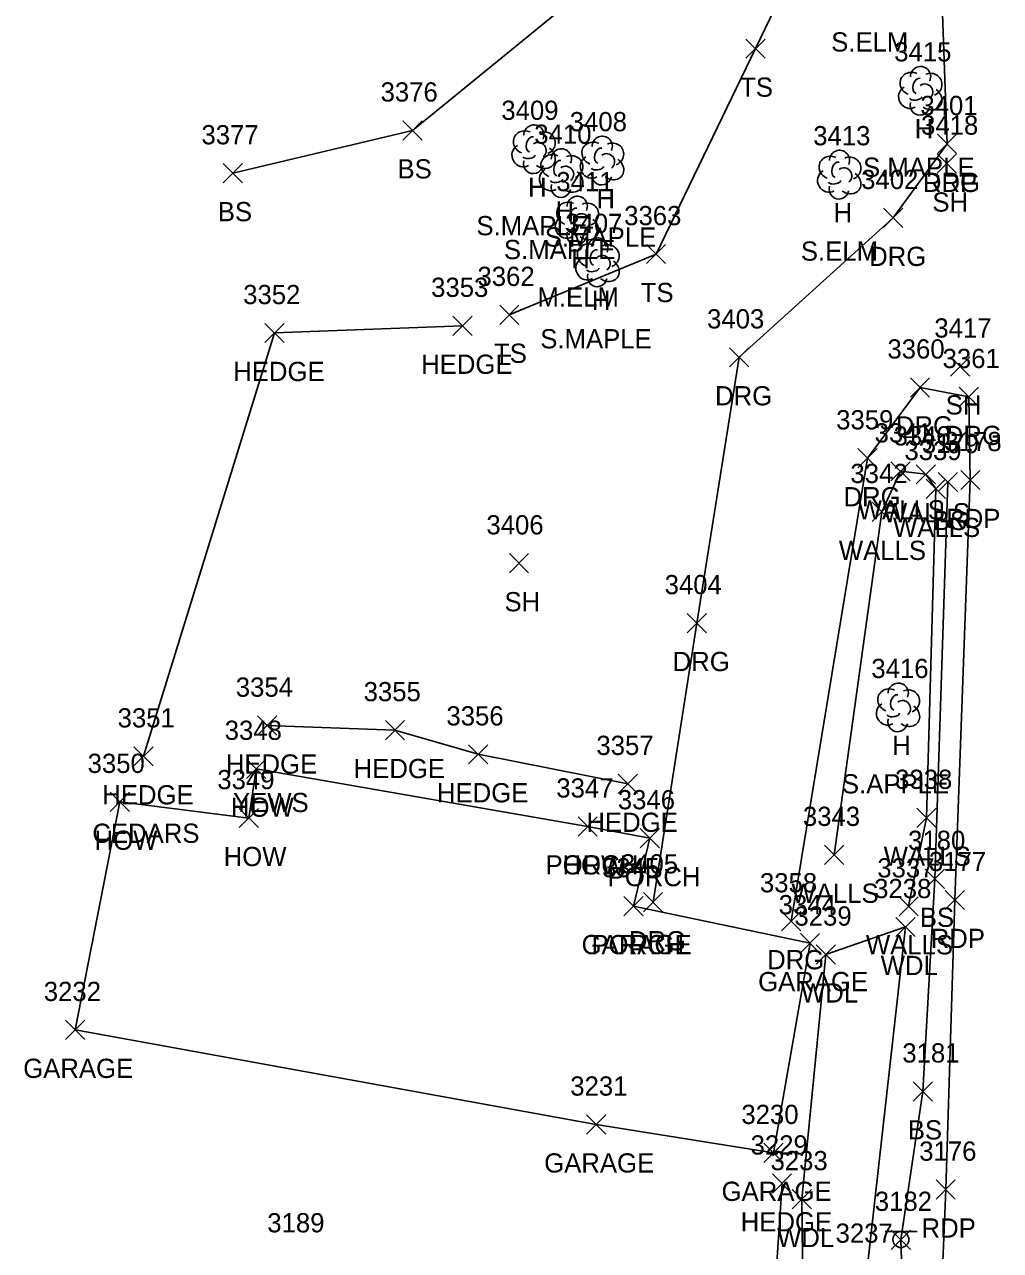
# Model space of a CAD drawing. Extents: x 1609623 to 1616187, y 756677 to 762826.
# Drawn here: x 1610505.2 to 1610606.7, y 762355.6 to 762483.1 of the extents above; entities that cross this region are included whole.
import ezdxf

# ---------------------------------------------------------------- set-up
doc = ezdxf.new("R2010")
doc.units = 0
for name, color, linetype in [('L_A', 7, 'Continuous'), ('L_C', 7, 'Continuous'), ('L_I', 7, 'Continuous'), ('L_TIC', 7, 'Continuous'), ('LAHR', 7, 'Continuous'), ('LAWA', 7, 'Continuous'), ('LBC', 7, 'Continuous'), ('LBF', 7, 'Continuous'), ('LELB', 7, 'Continuous'), ('LTD', 7, 'Continuous'), ('LWS', 7, 'Continuous'), ('P_A', 7, 'Continuous'), ('P_I', 7, 'Continuous'), ('P_TIC', 7, 'Continuous'), ('PET', 7, 'Continuous'), ('R_A', 7, 'Continuous'), ('R_I', 7, 'Continuous'), ('R_TIC', 7, 'Continuous'), ('RDG', 7, 'Continuous'), ('S_I', 7, 'Continuous'), ('SSGN', 7, 'Continuous')]:
    doc.layers.add(name, color=color, linetype=linetype)

msp = doc.modelspace()

# ---------------------------------------------------------------- linework, layer by layer
at = {"layer": 'L_TIC'}
for points in [[(1610580.23, 762479.58), (1610582.23, 762481.58)], [(1610582.23, 762479.58), (1610580.23, 762481.58)], [(1610544.56, 762471.08), (1610546.56, 762473.08)], [(1610546.56, 762471.08), (1610544.56, 762473.08)], [(1610600.15, 762467.63), (1610602.15, 762469.63)], [(1610602.15, 762467.63), (1610600.15, 762469.63)], [(1610525.87, 762466.63), (1610527.87, 762468.63)], [(1610527.87, 762466.63), (1610525.87, 762468.63)], [(1610569.89, 762458.22), (1610571.89, 762460.22)], [(1610571.89, 762458.22), (1610569.89, 762460.22)], [(1610554.63, 762451.9), (1610556.63, 762453.9)], [(1610556.63, 762451.9), (1610554.63, 762453.9)], [(1610530.21, 762450.01), (1610532.21, 762452.01)], [(1610532.21, 762450.01), (1610530.21, 762452.01)], [(1610549.76, 762450.76), (1610551.76, 762452.76)], [(1610551.76, 762450.76), (1610549.76, 762452.76)], [(1610601.53, 762446.53), (1610603.53, 762448.53)], [(1610603.53, 762446.53), (1610601.53, 762448.53)], [(1610595.32, 762435.62), (1610597.32, 762437.62)], [(1610597.32, 762435.62), (1610595.32, 762437.62)], [(1610597.95, 762435.31), (1610599.95, 762437.31)], [(1610599.95, 762435.31), (1610597.95, 762437.31)], [(1610600.24, 762434.51), (1610602.24, 762436.51)], [(1610602.24, 762434.51), (1610600.24, 762436.51)], [(1610599, 762433.79), (1610601, 762435.79)], [(1610601, 762433.79), (1610599, 762435.79)], [(1610593.37, 762431.4), (1610595.37, 762433.4)], [(1610595.37, 762431.4), (1610593.37, 762433.4)], [(1610555.64, 762426.06), (1610557.64, 762428.06)], [(1610557.64, 762426.06), (1610555.64, 762428.06)], [(1610529.44, 762409.18), (1610531.44, 762411.18)], [(1610531.44, 762409.18), (1610529.44, 762411.18)], [(1610542.74, 762408.71), (1610544.74, 762410.71)], [(1610544.74, 762408.71), (1610542.74, 762410.71)], [(1610516.59, 762405.98), (1610518.59, 762407.98)], [(1610518.59, 762405.98), (1610516.59, 762407.98)], [(1610551.4, 762406.19), (1610553.4, 762408.19)], [(1610553.4, 762406.19), (1610551.4, 762408.19)], [(1610528.29, 762404.69), (1610530.29, 762406.69)], [(1610530.29, 762404.69), (1610528.29, 762406.69)], [(1610566.95, 762403.12), (1610568.95, 762405.12)], [(1610568.95, 762403.12), (1610566.95, 762405.12)], [(1610514.11, 762401.25), (1610516.11, 762403.25)], [(1610516.11, 762401.25), (1610514.11, 762403.25)], [(1610527.53, 762399.56), (1610529.53, 762401.56)], [(1610529.53, 762399.56), (1610527.53, 762401.56)], [(1610598.02, 762399.59), (1610600.02, 762401.59)], [(1610600.02, 762399.59), (1610598.02, 762401.59)], [(1610562.78, 762398.69), (1610564.78, 762400.69)], [(1610564.78, 762398.69), (1610562.78, 762400.69)], [(1610562.78, 762398.69), (1610564.78, 762400.69)], [(1610564.78, 762398.69), (1610562.78, 762400.69)], [(1610569.24, 762397.47), (1610571.24, 762399.47)], [(1610571.24, 762397.47), (1610569.24, 762399.47)], [(1610588.43, 762395.74), (1610590.43, 762397.74)], [(1610590.43, 762395.74), (1610588.43, 762397.74)], [(1610598.89, 762393.24), (1610600.89, 762395.24)], [(1610600.89, 762393.24), (1610598.89, 762395.24)], [(1610567.55, 762390.4), (1610569.55, 762392.4)], [(1610569.55, 762390.4), (1610567.55, 762392.4)], [(1610567.55, 762390.4), (1610569.55, 762392.4)], [(1610569.55, 762390.4), (1610567.55, 762392.4)], [(1610596.17, 762390.38), (1610598.17, 762392.38)], [(1610598.17, 762390.38), (1610596.17, 762392.38)], [(1610595.84, 762388.23), (1610597.84, 762390.23)], [(1610597.84, 762388.23), (1610595.84, 762390.23)], [(1610585.91, 762386.55), (1610587.91, 762388.55)], [(1610587.91, 762386.55), (1610585.91, 762388.55)], [(1610587.56, 762385.37), (1610589.56, 762387.37)], [(1610589.56, 762385.37), (1610587.56, 762387.37)], [(1610509.47, 762377.53), (1610511.47, 762379.53)], [(1610511.47, 762377.53), (1610509.47, 762379.53)], [(1610597.64, 762371.13), (1610599.64, 762373.13)], [(1610599.64, 762371.13), (1610597.64, 762373.13)], [(1610563.67, 762367.69), (1610565.67, 762369.69)], [(1610565.67, 762367.69), (1610563.67, 762369.69)], [(1610582.11, 762364.74), (1610584.11, 762366.74)], [(1610584.11, 762364.74), (1610582.11, 762366.74)], [(1610583, 762361.56), (1610585, 762363.56)], [(1610585, 762361.56), (1610583, 762363.56)], [(1610585.06, 762359.93), (1610587.06, 762361.93)], [(1610587.06, 762359.93), (1610585.06, 762361.93)], [(1610595.35, 762355.7), (1610597.35, 762357.7)], [(1610597.35, 762355.7), (1610595.35, 762357.7)]]:
    msp.add_lwpolyline(points, dxfattribs=at)
at = {"layer": 'LAHR'}
for points in [[(1610517.59, 762406.98), (1610531.21, 762451.01), (1610550.76, 762451.76)], [(1610530.44, 762410.18), (1610543.74, 762409.71), (1610552.4, 762407.19), (1610567.95, 762404.12)], [(1610582.46, 762307.18), (1610581.3, 762322.56), (1610584, 762362.56)]]:
    msp.add_lwpolyline(points, dxfattribs=at)
at = {"layer": 'LAWA'}
for points in [[(1610586.06, 762360.93), (1610586.43, 762328.14), (1610588.36, 762309.19), (1610592.62, 762314.71), (1610592.83, 762353.39), (1610596.84, 762389.23), (1610588.56, 762386.37)], [(1610588.56, 762386.37), (1610586.06, 762360.93)]]:
    msp.add_lwpolyline(points, dxfattribs=at)
at = {"layer": 'LBC'}
for points in [[(1610563.78, 762399.69), (1610529.29, 762405.69), (1610528.53, 762400.56), (1610515.11, 762402.25)], [(1610515.11, 762402.25), (1610510.47, 762378.53)], [(1610586.91, 762387.55), (1610568.55, 762391.4)], [(1610586.91, 762387.55), (1610583.11, 762365.74)], [(1610583.11, 762365.74), (1610564.67, 762368.69), (1610510.47, 762378.53)]]:
    msp.add_lwpolyline(points, dxfattribs=at)
at = {"layer": 'LBF'}
msp.add_lwpolyline([(1610568.55, 762391.4), (1610570.24, 762398.47), (1610563.78, 762399.69)], dxfattribs=at)
at = {"layer": 'LELB'}
for points in [[(1610555.63, 762452.9), (1610570.89, 762459.22), (1610581.23, 762480.58), (1610591.33, 762501.51), (1610590.52, 762530.81), (1610583.83, 762554.19), (1610570.39, 762605.11)], [(1610574.84, 762534.79), (1610575.41, 762508.59), (1610574.59, 762505.74), (1610568.05, 762490.43), (1610545.56, 762472.08), (1610526.87, 762467.63)], [(1610601.24, 762435.51), (1610599.89, 762394.24), (1610598.64, 762372.13), (1610596.35, 762356.7), (1610597.27, 762330.15), (1610594.16, 762309.47), (1610581.81, 762305.45), (1610558.47, 762312.1), (1610535.64, 762323.35), (1610518.75, 762343.55), (1610533.17, 762354.47)]]:
    msp.add_lwpolyline(points, dxfattribs=at)
at = {"layer": 'LTD'}
for p, q in [((1610598.36, 762476.25), (1610598.36, 762476.25)), ((1610598.36, 762476.25), (1610598.36, 762476.25)), ((1610558.14, 762470.17), (1610558.14, 762470.17)), ((1610558.14, 762470.17), (1610558.14, 762470.17)), ((1610565.26, 762468.99), (1610565.26, 762468.99)), ((1610565.26, 762468.99), (1610565.26, 762468.99)), ((1610561, 762467.69), (1610561, 762467.69)), ((1610561, 762467.69), (1610561, 762467.69)), ((1610589.93, 762467.53), (1610589.93, 762467.53)), ((1610589.93, 762467.53), (1610589.93, 762467.53)), ((1610562.65, 762462.75), (1610562.65, 762462.75)), ((1610562.65, 762462.75), (1610562.65, 762462.75)), ((1610564.79, 762458.41), (1610564.79, 762458.41)), ((1610564.79, 762458.41), (1610564.79, 762458.41)), ((1610596.04, 762412.12), (1610596.04, 762412.12)), ((1610596.04, 762412.12), (1610596.04, 762412.12))]:
    msp.add_line(p, q, dxfattribs=at)
for centre in [(1610598.41, 762477.68), (1610558.19, 762471.6), (1610565.3, 762470.43), (1610561.05, 762469.12), (1610589.98, 762468.96), (1610562.7, 762464.18), (1610564.84, 762459.84), (1610596.09, 762413.55)]:
    msp.add_arc(centre, 1.05, 335.5272, 180.9563, dxfattribs=at)
for centre, major_axis, ratio, start_param, end_param in [((1610597.57, 762476.92), (1.21, -0.51), 0.895232, 1.570796, 4.712389), ((1610598.16, 762476.71), (-0.208, -0.792), 0.645439, 3.141593, 6.283185), ((1610599.41, 762476.83), (-1.14, -0.48), 0.949671, 1.570796, 4.712389), ((1610597.28, 762475.54), (0.58, -1.04), 0.959034, 3.141593, 6.283185), ((1610598.86, 762476.08), (-0.5, 0.667), 0.989748, 3.141593, 6.283185), ((1610599.36, 762475.42), (-1.09, 0.79), 0.841452, 1.570796, 4.712389), ((1610598.36, 762474.75), (0.26, 1.06), 0.942809, 1.570796, 4.712389), ((1610597.91, 762475.5), (-0.625, -0.083), 0.423636, 0, 3.141593), ((1610557.35, 762470.83), (1.21, -0.51), 0.895232, 1.570796, 4.712389), ((1610557.94, 762470.62), (-0.208, -0.792), 0.645439, 3.141593, 6.283185), ((1610558.64, 762470), (-0.5, 0.667), 0.989748, 3.141593, 6.283185), ((1610559.19, 762470.75), (-1.14, -0.48), 0.949671, 1.570796, 4.712389), ((1610564.47, 762469.66), (1.21, -0.51), 0.895232, 1.570796, 4.712389), ((1610566.3, 762469.58), (-1.14, -0.48), 0.949671, 1.570796, 4.712389), ((1610557.06, 762469.46), (0.58, -1.04), 0.959034, 3.141593, 6.283185), ((1610559.14, 762469.33), (-1.09, 0.79), 0.841452, 1.570796, 4.712389), ((1610560.21, 762468.36), (1.21, -0.51), 0.895232, 1.570796, 4.712389), ((1610562.05, 762468.27), (-1.14, -0.48), 0.949671, 1.570796, 4.712389), ((1610565.05, 762469.45), (-0.208, -0.792), 0.645439, 3.141593, 6.283185), ((1610565.76, 762468.83), (-0.5, 0.667), 0.989748, 3.141593, 6.283185), ((1610558.14, 762468.67), (0.26, 1.06), 0.942809, 1.570796, 4.712389), ((1610557.69, 762469.42), (-0.625, -0.083), 0.423636, 0, 3.141593), ((1610560.8, 762468.15), (-0.208, -0.792), 0.645439, 3.141593, 6.283185), ((1610561.5, 762467.52), (-0.5, 0.667), 0.989748, 3.141593, 6.283185), ((1610564.17, 762468.28), (0.58, -1.04), 0.959034, 3.141593, 6.283185), ((1610564.8, 762468.24), (-0.625, -0.083), 0.423636, 0, 3.141593), ((1610566.26, 762468.16), (-1.09, 0.79), 0.841452, 1.570796, 4.712389), ((1610589.14, 762468.19), (1.21, -0.51), 0.895232, 1.570796, 4.712389), ((1610589.72, 762467.98), (-0.208, -0.792), 0.645439, 3.141593, 6.283185), ((1610590.97, 762468.11), (-1.14, -0.48), 0.949671, 1.570796, 4.712389), ((1610559.92, 762466.98), (0.58, -1.04), 0.959034, 3.141593, 6.283185), ((1610562.01, 762466.86), (-1.09, 0.79), 0.841452, 1.570796, 4.712389), ((1610565.26, 762467.49), (0.26, 1.06), 0.942809, 1.570796, 4.712389), ((1610588.85, 762466.82), (0.58, -1.04), 0.959034, 3.141593, 6.283185), ((1610590.43, 762467.36), (-0.5, 0.667), 0.989748, 3.141593, 6.283185), ((1610590.93, 762466.69), (-1.09, 0.79), 0.841452, 1.570796, 4.712389), ((1610561.01, 762466.19), (0.26, 1.06), 0.942809, 1.570796, 4.712389), ((1610560.55, 762466.94), (-0.625, -0.083), 0.423636, 0, 3.141593), ((1610589.93, 762466.03), (0.26, 1.06), 0.942809, 1.570796, 4.712389), ((1610589.47, 762466.78), (-0.625, -0.083), 0.423636, 0, 3.141593), ((1610561.86, 762463.41), (1.21, -0.51), 0.895232, 1.570796, 4.712389), ((1610563.69, 762463.33), (-1.14, -0.48), 0.949671, 1.570796, 4.712389), ((1610562.44, 762463.21), (-0.208, -0.792), 0.645439, 3.141593, 6.283185), ((1610563.15, 762462.58), (-0.5, 0.667), 0.989748, 3.141593, 6.283185), ((1610561.57, 762462.04), (0.58, -1.04), 0.959034, 3.141593, 6.283185), ((1610562.19, 762462), (-0.625, -0.083), 0.423636, 0, 3.141593), ((1610563.65, 762461.91), (-1.09, 0.79), 0.841452, 1.570796, 4.712389), ((1610562.65, 762461.25), (0.26, 1.06), 0.942809, 1.570796, 4.712389), ((1610564, 762459.07), (1.21, -0.51), 0.895232, 1.570796, 4.712389), ((1610564.58, 762458.87), (-0.208, -0.792), 0.645439, 3.141593, 6.283185), ((1610565.83, 762458.99), (-1.14, -0.48), 0.949671, 1.570796, 4.712389), ((1610563.71, 762457.7), (0.58, -1.04), 0.959034, 3.141593, 6.283185), ((1610565.29, 762458.24), (-0.5, 0.667), 0.989748, 3.141593, 6.283185), ((1610565.79, 762457.57), (-1.09, 0.79), 0.841452, 1.570796, 4.712389), ((1610564.79, 762456.91), (0.26, 1.06), 0.942809, 1.570796, 4.712389), ((1610564.33, 762457.66), (-0.625, -0.083), 0.423636, 0, 3.141593), ((1610595.25, 762412.79), (1.21, -0.51), 0.895232, 1.570796, 4.712389), ((1610597.08, 762412.7), (-1.14, -0.48), 0.949671, 1.570796, 4.712389), ((1610594.96, 762411.41), (0.58, -1.04), 0.959034, 3.141593, 6.283185), ((1610595.83, 762412.58), (-0.208, -0.792), 0.645439, 3.141593, 6.283185), ((1610596.54, 762411.95), (-0.5, 0.667), 0.989748, 3.141593, 6.283185), ((1610595.58, 762411.37), (-0.625, -0.083), 0.423636, 0, 3.141593), ((1610597.04, 762411.29), (-1.09, 0.79), 0.841452, 1.570796, 4.712389), ((1610596.04, 762410.62), (0.26, 1.06), 0.942809, 1.570796, 4.712389)]:
    msp.add_ellipse(centre, major_axis=major_axis, ratio=ratio, start_param=start_param, end_param=end_param, dxfattribs=at)
at = {"layer": 'LWS'}
msp.add_lwpolyline([(1610597.17, 762391.38), (1610599.02, 762400.59), (1610600, 762434.79), (1610598.95, 762436.31), (1610596.32, 762436.62), (1610594.37, 762432.4), (1610589.43, 762396.74)], dxfattribs=at)
at = {"layer": 'P_TIC'}
for points in [[(1610600.16, 762469.67), (1610602.16, 762471.67)], [(1610602.16, 762469.67), (1610600.16, 762471.67)], [(1610602.58, 762434.72), (1610604.58, 762436.72)], [(1610604.58, 762434.72), (1610602.58, 762436.72)], [(1610600.97, 762391.04), (1610602.97, 762393.04)], [(1610602.97, 762391.04), (1610600.97, 762393.04)], [(1610600.02, 762360.92), (1610602.02, 762362.92)], [(1610602.02, 762360.92), (1610600.02, 762362.92)]]:
    msp.add_lwpolyline(points, dxfattribs=at)
at = {"layer": 'PET'}
for points in [[(1610534.83, 762671.35), (1610542.81, 762660.78), (1610568.73, 762619.92), (1610585.48, 762582.39), (1610594.75, 762542.34), (1610600.31, 762494.84), (1610601.16, 762470.67)], [(1610595.04, 762218.43), (1610595.92, 762250), (1610597.03, 762268.03), (1610599.19, 762317.84), (1610601.02, 762361.92), (1610601.97, 762392.04), (1610603.58, 762435.72)]]:
    msp.add_lwpolyline(points, dxfattribs=at)
at = {"layer": 'R_TIC'}
for points in [[(1610600.16, 762469.67), (1610602.16, 762471.67)], [(1610602.16, 762469.67), (1610600.16, 762471.67)], [(1610594.57, 762461.98), (1610596.57, 762463.98)], [(1610596.57, 762461.98), (1610594.57, 762463.98)], [(1610578.54, 762447.48), (1610580.54, 762449.48)], [(1610580.54, 762447.48), (1610578.54, 762449.48)], [(1610597.35, 762444.35), (1610599.35, 762446.35)], [(1610599.35, 762444.35), (1610597.35, 762446.35)], [(1610602.44, 762443.36), (1610604.44, 762445.36)], [(1610604.44, 762443.36), (1610602.44, 762445.36)], [(1610591.9, 762436.98), (1610593.9, 762438.98)], [(1610593.9, 762436.98), (1610591.9, 762438.98)], [(1610574.13, 762419.84), (1610576.13, 762421.84)], [(1610576.13, 762419.84), (1610574.13, 762421.84)], [(1610569.58, 762390.8), (1610571.58, 762392.8)], [(1610571.58, 762390.8), (1610569.58, 762392.8)], [(1610583.96, 762388.83), (1610585.96, 762390.83)], [(1610585.96, 762388.83), (1610583.96, 762390.83)]]:
    msp.add_lwpolyline(points, dxfattribs=at)
at = {"layer": 'RDG'}
for points in [[(1610601.16, 762470.67), (1610595.57, 762462.98), (1610579.54, 762448.48), (1610575.13, 762420.84), (1610570.58, 762391.8)], [(1610584.96, 762389.83), (1610592.9, 762437.98), (1610598.35, 762445.35), (1610603.44, 762444.36)], [(1610603.44, 762444.36), (1610603.58, 762435.72)]]:
    msp.add_lwpolyline(points, dxfattribs=at)
at = {"layer": 'SSGN'}
for p, q in [((1610594.72, 762357.56), (1610598.05, 762357.56)), ((1610596.36, 762356.72), (1610596.36, 762356.72))]:
    msp.add_line(p, q, dxfattribs=at)
msp.add_circle((1610596.36, 762356.72), 0.833, dxfattribs=at)

# ---------------------------------------------------------------- texts
at = {"layer": 'L_A'}
for s, p in [('TS', (1610579.64, 762475.58)), ('H', (1610597.8, 762471.25)), ('BS', (1610544, 762467.08)), ('H', (1610557.58, 762465.17)), ('H', (1610564.69, 762463.99)), ('BS', (1610525.31, 762462.63)), ('H', (1610560.44, 762462.69)), ('H', (1610589.36, 762462.53)), ('SH', (1610599.64, 762463.63)), ('H', (1610562.08, 762457.75)), ('TS', (1610569.3, 762454.22)), ('H', (1610564.22, 762453.41)), ('TS', (1610554.04, 762447.9)), ('HEDGE', (1610526.91, 762446.01)), ('HEDGE', (1610546.46, 762446.76)), ('SH', (1610601.02, 762442.53)), ('WALLS', (1610591.87, 762431.62)), ('WALLS', (1610594.49, 762431.31)), ('WALLS', (1610595.54, 762429.79)), ('BS', (1610599.68, 762430.51)), ('WALLS', (1610589.91, 762427.4)), ('SH', (1610555.13, 762422.06)), ('H', (1610595.47, 762407.12)), ('HEDGE', (1610526.14, 762405.18)), ('HEDGE', (1610539.44, 762404.71)), ('HEDGE', (1610513.29, 762401.98)), ('HEDGE', (1610548.1, 762402.19)), ('HOW', (1610526.68, 762400.69)), ('HEDGE', (1610563.65, 762399.12)), ('HOW', (1610512.5, 762397.25)), ('HOW', (1610525.92, 762395.56)), ('WALLS', (1610594.57, 762395.59)), ('PORCH', (1610559.4, 762394.69)), ('HOW', (1610561.16, 762394.69)), ('PORCH', (1610565.86, 762393.47)), ('WALLS', (1610584.98, 762391.74)), ('BS', (1610598.33, 762389.24)), ('GARAGE', (1610563.15, 762386.4)), ('PORCH', (1610564.17, 762386.4)), ('WALLS', (1610592.72, 762386.38)), ('WDL', (1610594.26, 762384.23)), ('GARAGE', (1610581.51, 762382.55)), ('WDL', (1610585.97, 762381.37)), ('GARAGE', (1610505.07, 762373.53)), ('BS', (1610597.08, 762367.13)), ('GARAGE', (1610559.26, 762363.69)), ('GARAGE', (1610577.71, 762360.74)), ('HEDGE', (1610579.7, 762357.56)), ('WDL', (1610583.48, 762355.93))]:
    msp.add_text(s, height=2, dxfattribs=at).set_placement(p)
at = {"layer": 'L_C'}
for s, p in [('S.ELM', (1610589.11, 762480.28)), ('S.MAPLE', (1610592.43, 762467.25)), ('S.MAPLE', (1610552.21, 762461.17)), ('S.MAPLE', (1610559.32, 762459.99)), ('S.MAPLE', (1610555.07, 762458.69)), ('S.ELM', (1610585.96, 762458.53)), ('M.ELM', (1610558.56, 762453.75)), ('S.MAPLE', (1610558.85, 762449.41)), ('S.APPLE', (1610590.23, 762403.12)), ('YEWS', (1610526.89, 762401.18)), ('CEDARS', (1610512.26, 762397.98))]:
    msp.add_text(s, height=2, dxfattribs=at).set_placement(p)
at = {"layer": 'L_I'}
for s, p in [('3415', (1610595.67, 762479.25)), ('3376', (1610542.24, 762475.08)), ('3409', (1610554.8, 762473.17)), ('3408', (1610561.92, 762471.99)), ('3418', (1610598.46, 762471.63)), ('3377', (1610523.61, 762470.63)), ('3410', (1610558.23, 762470.69)), ('3413', (1610587.24, 762470.53)), ('3411', (1610560.52, 762465.75)), ('3407', (1610561.45, 762461.41)), ('3363', (1610567.58, 762462.22)), ('3362', (1610552.32, 762455.9)), ('3352', (1610527.95, 762454.01)), ('3353', (1610547.5, 762454.76)), ('3417', (1610599.84, 762450.53)), ('3341', (1610593.63, 762439.62)), ('3340', (1610595.6, 762439.31)), ('3179', (1610598.54, 762438.51)), ('3339', (1610596.73, 762437.79)), ('3342', (1610591.11, 762435.4)), ('3406', (1610553.25, 762430.06)), ('3416', (1610593.29, 762415.12)), ('3354', (1610527.18, 762413.18)), ('3355', (1610540.48, 762412.71)), ('3356', (1610549.09, 762410.19)), ('3351', (1610514.89, 762409.98)), ('3348', (1610526.03, 762408.69)), ('3357', (1610564.69, 762407.12)), ('3350', (1610511.77, 762405.25)), ('3349', (1610525.26, 762403.56)), ('3347', (1610560.52, 762402.69)), ('3347', (1610560.52, 762402.69)), ('3338', (1610595.76, 762403.59)), ('3346', (1610566.92, 762401.47)), ('3343', (1610586.17, 762399.74)), ('3180', (1610597.11, 762397.24)), ('3345', (1610565.29, 762394.4)), ('3345', (1610565.29, 762394.4)), ('3337', (1610593.91, 762394.38)), ('3238', (1610593.58, 762392.23)), ('3344', (1610583.65, 762390.55)), ('3239', (1610585.29, 762389.37)), ('3232', (1610507.21, 762381.53)), ('3181', (1610596.51, 762375.13)), ('3231', (1610561.97, 762371.69)), ('3230', (1610579.77, 762368.74)), ('3229', (1610580.73, 762365.56)), ('3233', (1610582.8, 762363.93)), ('3182', (1610593.65, 762359.7)), ('3189', (1610530.46, 762357.47)), ('3189', (1610530.46, 762357.47)), ('3237', (1610589.57, 762356.39))]:
    msp.add_text(s, height=2, dxfattribs=at).set_placement(p)
at = {"layer": 'P_A'}
for p in [(1610598.65, 762465.67), (1610601.07, 762430.72), (1610599.46, 762387.04), (1610598.51, 762356.92)]:
    msp.add_text('RDP', height=2, dxfattribs=at).set_placement(p)
at = {"layer": 'P_I'}
for s, p in [('3401', (1610598.39, 762473.67)), ('3178', (1610600.89, 762438.72)), ('3177', (1610599.28, 762395.04)), ('3176', (1610598.27, 762364.92))]:
    msp.add_text(s, height=2, dxfattribs=at).set_placement(p)
at = {"layer": 'R_A'}
for p in [(1610598.65, 762465.67), (1610593.06, 762457.98), (1610577.03, 762443.48), (1610595.84, 762440.35), (1610600.93, 762439.36), (1610590.39, 762432.98), (1610572.62, 762415.84), (1610568.07, 762386.8), (1610582.45, 762384.83)]:
    msp.add_text('DRG', height=2, dxfattribs=at).set_placement(p)
at = {"layer": 'R_I'}
for s, p in [('3401', (1610598.39, 762473.67)), ('3402', (1610592.23, 762465.98)), ('3403', (1610576.2, 762451.48)), ('3360', (1610594.96, 762448.35)), ('3361', (1610600.7, 762447.36)), ('3359', (1610589.63, 762440.98)), ('3404', (1610571.79, 762423.84)), ('3405', (1610567.24, 762394.8)), ('3358', (1610581.7, 762392.83))]:
    msp.add_text(s, height=2, dxfattribs=at).set_placement(p)
at = {"layer": 'S_I'}
msp.add_text('3182', height=2, dxfattribs=at).set_placement((1610593.65, 762359.7))

doc.saveas('drawing.dxf')
